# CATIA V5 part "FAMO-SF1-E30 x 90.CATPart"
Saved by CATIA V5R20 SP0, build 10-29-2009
Part number: FAMO-SF1-E30 x 90
Definition: NONE
Nomenclature: FAMO-SF1-E30 x 90
Source: Unknown
Description: FAMO-SF1-E30 x 90
Bounding box of the stored display mesh (mm): x -64 to 26, y -26.5 to 26.5, z -26.5 to 26.5
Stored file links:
  C:\Users\Utente\Desktop\IO LAVORO\3D X SITO CF\X SITO\FAMO\FAMO-SF1-E30 x 90.CATPart
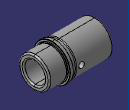
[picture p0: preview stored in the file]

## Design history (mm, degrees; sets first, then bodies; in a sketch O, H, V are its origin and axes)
Body1 "FAMO-SF1-E30 x 90" (main body)
  Solid1: solid without history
